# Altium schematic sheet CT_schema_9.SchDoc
size 254 x 194 mm
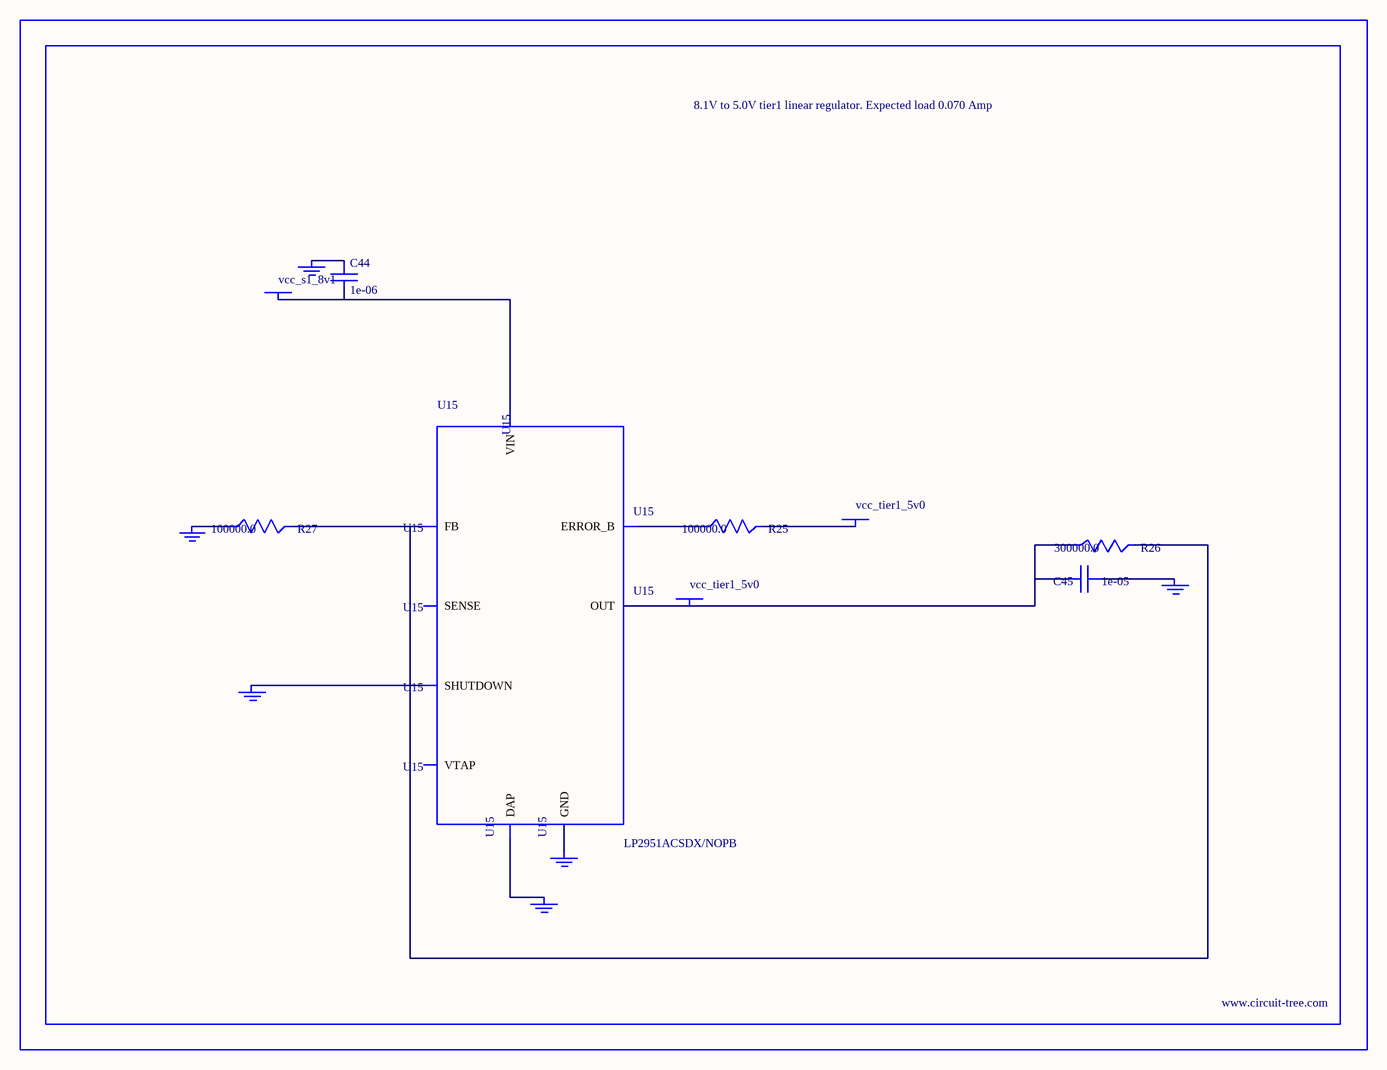
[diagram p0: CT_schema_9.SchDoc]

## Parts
BORDER8  (no value)
C44  1e-06  [C0603]
C45  1e-05  [C1210]
GND_INSTANCE_8_0  (no value)
GND_INSTANCE_8_1  (no value)
GND_INSTANCE_8_2  (no value)
GND_INSTANCE_8_3  (no value)
GND_INSTANCE_8_4  (no value)
GND_INSTANCE_8_5  (no value)
POWER_INSTANCE_8_0  vcc_tier1_5v0
POWER_INSTANCE_8_1  vcc_s1_8v1
POWER_INSTANCE_8_2  vcc_tier1_5v0
R25  100000.0  [R0603]
R26  300000.0  [R0603]
R27  100000.0  [R0603]
U15  LP2951ACSDX/NOPB  [WSON-8]

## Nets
NetC44_1: C44.1 GND_INSTANCE_8_3.0(GND)
NetC44_2: C44.2 POWER_INSTANCE_8_1.0(PWR) U15.8(VIN)
NetC45_1: C45.1 GND_INSTANCE_8_0.0(GND)
NetC45_2: C45.2 POWER_INSTANCE_8_2.0(PWR) R26.1 U15.1(OUT)
NetGND_INSTANCE_8_1_0: GND_INSTANCE_8_1.0(GND) U15.3(SHUTDOWN)
NetGND_INSTANCE_8_2_0: GND_INSTANCE_8_2.0(GND) R27.1
NetGND_INSTANCE_8_4_0: GND_INSTANCE_8_4.0(GND) U15.PAD(DAP)
NetGND_INSTANCE_8_5_0: GND_INSTANCE_8_5.0(GND) U15.4(GND)
NetPOWER_INSTANCE_8_0_0: POWER_INSTANCE_8_0.0(PWR) R25.2
NetR25_1: R25.1 U15.5(ERROR_B)
NetR26_2: R26.2 R27.2 U15.7(FB)

Not connected (* = marked no-connect by the designer): U15 2(SENSE) 6(VTAP)

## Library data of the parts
BORDER8 = BORDER_PAGE8
C44 = C0603C105K3RACTU
C45 = GRM32DR61E106MA12L
GND_INSTANCE_8_0-GND_INSTANCE_8_5 = GND
POWER_INSTANCE_8_0-POWER_INSTANCE_8_2 = PWR
R25 R27 = RC0603JR-07100KL
R26 = RC0603JR-07300KL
